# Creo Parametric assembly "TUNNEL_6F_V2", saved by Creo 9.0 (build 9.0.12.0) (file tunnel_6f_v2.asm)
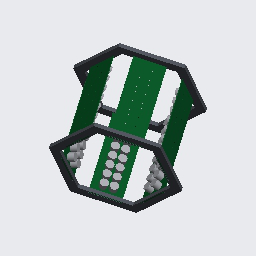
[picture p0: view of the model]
Units: millimeter Newton Second (mmNs); MM, TONNE, SECS

Created from: XX_MMNS_ASM_DESIGN_ABS.ASM

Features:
  1. datum plane "ASM_RIGHT"
  2. datum plane "ASM_TOP"
  3. datum plane "ASM_FRONT"
  4. coordinate system
  5. coordinate system
  6. component "PANEL_6F"
  7. coordinate system
  8. component "PANEL_6F"
  9. coordinate system
  10. component "PANEL_6F"
  11. coordinate system
  12. component "PANEL_6F"
  13. coordinate system
  14. component "PANEL_6F"
  15. coordinate system
  16. component "PANEL_6F"
  17. coordinate system
  18. component "RING_6F"
  19. coordinate system
  20. component "RING_6F"

Other named items: ACS0, ACS1, ACS2, ACS3, ACS4, ACS5, ACS6, ACS7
